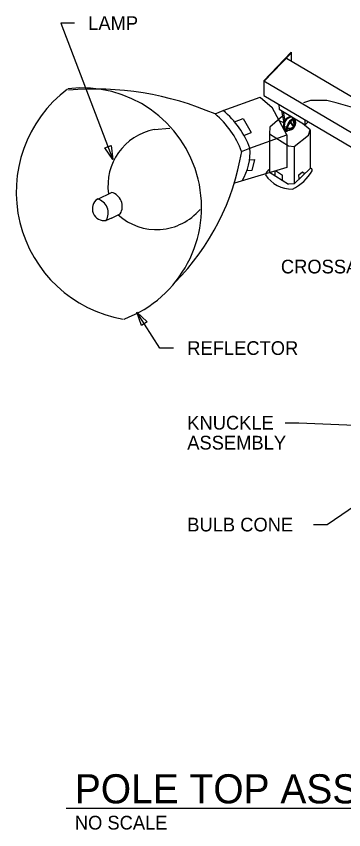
# Model space of a CAD drawing. Extents: x 10378 to 10425.2, y 10088.7 to 10132.4.
# Drawn here: x 10378.04 to 10393.97, y 10089.98 to 10129.52 of the extents above; entities that cross this region are included whole.
import ezdxf

# ---------------------------------------------------------------- set-up
doc = ezdxf.new("R2010")
doc.units = 0
for name, color, linetype in [('G-ANNO-TEXT', 7, 'Continuous'), ('G-DETL-LINE', 7, 'Continuous'), ('G-DETL-OTLN', 7, 'Continuous'), ('G-DETL-PATT', 7, 'Continuous')]:
    doc.layers.add(name, color=color, linetype=linetype)

msp = doc.modelspace()

# ---------------------------------------------------------------- linework, layer by layer
at = {"layer": 'G-ANNO-TEXT'}
for p, q in [((10380.873, 10129.184), (10380.207, 10129.184)), ((10380.207, 10129.184), (10382.744, 10122.561)), ((10385.026, 10113.39), (10383.913, 10115.142)), ((10385.693, 10113.39), (10385.026, 10113.39)), ((10391.126, 10109.759), (10391.793, 10109.759)), ((10391.793, 10109.759), (10398.213, 10109.494)), ((10393.168, 10104.808), (10398.04, 10108.165)), ((10392.501, 10104.808), (10393.168, 10104.808)), ((10380.467, 10091.02), (10423.113, 10091.02))]:
    msp.add_line(p, q, dxfattribs=at)
for points in [[(10382.662, 10123.243), (10382.744, 10122.561), (10382.35, 10123.123)], [(10384.13, 10114.49), (10383.913, 10115.142), (10384.411, 10114.668)]]:
    msp.add_lwpolyline(points, close=True, dxfattribs=at)
at = {"layer": 'G-DETL-LINE'}
for p, q in [((10390.82, 10125.223), (10390.825, 10124.995)), ((10390.997, 10124.669), (10390.382, 10124.131)), ((10390.825, 10124.995), (10392.095, 10124.233)), ((10390.945, 10124.923), (10391.062, 10124.348)), ((10391.028, 10124.873), (10391.113, 10124.457)), ((10390.847, 10124.436), (10391.065, 10124.348)), ((10392.334, 10123.998), (10391.973, 10124.305)), ((10392.095, 10124.233), (10392.095, 10124.471)), ((10392.095, 10124.233), (10392.249, 10124.38)), ((10390.382, 10124.131), (10390.356, 10123.81)), ((10390.971, 10124.177), (10391.217, 10124.136)), ((10391.125, 10123.966), (10391.161, 10123.978)), ((10391.125, 10123.893), (10391.125, 10123.966)), ((10391.161, 10123.893), (10391.161, 10123.978)), ((10391.179, 10123.893), (10391.179, 10124.038)), ((10391.215, 10123.893), (10391.215, 10124.049)), ((10392.253, 10123.73), (10392.334, 10123.998)), ((10392.334, 10123.998), (10392.334, 10122.125)), ((10390.356, 10123.81), (10390.356, 10121.938)), ((10390.356, 10123.81), (10391.291, 10123.222)), ((10391.558, 10123.195), (10392.253, 10123.73)), ((10391.291, 10123.222), (10391.558, 10123.195)), ((10391.558, 10123.195), (10391.558, 10121.376)), ((10390.356, 10121.938), (10391.291, 10121.349)), ((10390.63, 10121.766), (10390.63, 10121.998)), ((10390.651, 10122.022), (10391.001, 10121.786)), ((10392.334, 10122.125), (10391.558, 10121.376)), ((10391.78, 10121.811), (10391.959, 10121.96)), ((10391.959, 10121.96), (10392.067, 10121.868)), ((10391.001, 10121.534), (10391.001, 10121.786)), ((10391.798, 10121.617), (10391.78, 10121.811)), ((10391.558, 10121.376), (10391.291, 10121.349))]:
    msp.add_line(p, q, dxfattribs=at)
for centre, radius, start, end in [((10391.479, 10124.221), 0.436, 100.2717, 215.8313), ((10391.479, 10124.221), 0.4, 94.0056, 217.4608), ((10391.864, 10123.968), 0.688, 118.8543, 174.2368), ((10391.922, 10123.904), 0.722, 118.1089, 168.3754), ((10391.263, 10124.345), 0.375, 265.3953, 31.5556), ((10391.245, 10124.063), 0.289, 20.663, 69.297), ((10391.249, 10124.117), 0.281, 12.7976, 63.9539), ((10391.16, 10124.277), 0.395, 347.8326, 31.9067), ((10391.201, 10124.288), 0.395, 349.7008, 34.0489), ((10391.319, 10124.432), 0.356, 253.9647, 301.1435), ((10391.293, 10124.425), 0.382, 259.327, 302.5745), ((10391.632, 10124.093), 0.133, 95.1644, 192.366), ((10390.49, 10121.756), 0.328, 134.8398, 171.2692), ((10390.43, 10121.874), 0.207, 111.139, 146.0525), ((10390.434, 10123.197), 2.331, 296.6306, 329.3358), ((10392.358, 10122.042), 0.087, 337.3261, 106.4069), ((10391.467, 10122.683), 1.57, 213.9622, 270.399)]:
    msp.add_arc(centre, radius, start, end, dxfattribs=at)
at = {"layer": 'G-DETL-OTLN'}
for p, q in [((10390.083, 10126.387), (10391.421, 10127.779)), ((10390.109, 10126.363), (10391.421, 10127.728)), ((10391.182, 10127.479), (10424.91, 10107.581)), ((10391.421, 10127.779), (10391.421, 10127.339)), ((10390.083, 10126.387), (10390.083, 10125.666)), ((10390.083, 10126.387), (10423.843, 10106.471)), ((10388.113, 10124.931), (10389.912, 10125.589)), ((10389.912, 10125.589), (10390.49, 10125.085)), ((10390.083, 10125.666), (10423.843, 10105.749)), ((10391.208, 10123.759), (10390.49, 10125.085)), ((10387.711, 10124.77), (10388.113, 10124.931)), ((10388.656, 10124.391), (10389.076, 10124.556)), ((10389.076, 10124.556), (10389.468, 10123.862)), ((10384.753, 10124.009), (10385.506, 10124.071)), ((10389.119, 10123.725), (10389.468, 10123.862)), ((10389.408, 10123.1), (10391.208, 10123.759)), ((10391.208, 10123.759), (10391.212, 10122.17)), ((10389.006, 10122.939), (10389.408, 10123.1)), ((10389.388, 10122.537), (10389.628, 10122.562)), ((10389.628, 10122.562), (10389.503, 10122.028)), ((10391.212, 10122.17), (10388.651, 10121.409)), ((10389.503, 10122.028), (10389.256, 10121.998)), ((10382.009, 10120.63), (10382.672, 10120.956)), ((10382.682, 10119.709), (10382.418, 10119.594)), ((10382.682, 10119.709), (10383.099, 10119.908))]:
    msp.add_line(p, q, dxfattribs=at)
for centre, radius, start, end in [((10384.31, 10120.974), 6.27, 127.0508, 260.2516), ((10381.252, 10120.232), 5.802, 290.5252, 96.7772), ((10381.856, 10111.177), 14.8, 66.6981, 94.9636), ((10384.936, 10121.432), 4.34, 20.324, 50.2663), ((10385.338, 10121.593), 4.34, 20.324, 50.2663), ((10385.282, 10121.279), 2.781, 100.978, 188.121), ((10386.69, 10122.915), 2.725, 329.2732, 3.9034), ((10377.506, 10124.804), 11.651, 315.1694, 350.7902), ((10382.494, 10120.274), 0.705, 329.3691, 75.3618), ((10382.317, 10120.161), 0.576, 124.6885, 280.0424), ((10381.811, 10119.953), 0.705, 329.3691, 75.3618), ((10384.863, 10121.931), 2.781, 228.0701, 319.6224)]:
    msp.add_arc(centre, radius, start, end, dxfattribs=at)
at = {"layer": 'G-DETL-PATT'}
msp.add_lwpolyline([(10405.342, 10118.577), (10401.582, 10120.857), (10399.759, 10121.655), (10398.278, 10122.453), (10396.911, 10123.479), (10395.43, 10124.505), (10394.404, 10125.075), (10393.607, 10125.303), (10393.151, 10125.417), (10392.354, 10125.417), (10392.012, 10125.303)], dxfattribs=at)

# ---------------------------------------------------------------- texts
at = {"layer": 'G-ANNO-TEXT'}
for s, height, p in [('LAMP', 0.6667, (10381.54, 10128.851)), ('CROSSARM', 0.6667, (10390.915, 10117.017)), ('REFLECTOR', 0.6667, (10386.36, 10113.056)), ('KNUCKLE', 0.6667, (10386.36, 10109.426)), ('ASSEMBLY', 0.6667, (10386.36, 10108.457)), ('BULB CONE', 0.6667, (10386.36, 10104.475)), ('POLE TOP ASSEMBLY ELECTRICAL DETAIL', 1.41667, (10380.89, 10091.256)), ('NO SCALE', 0.6667, (10380.89, 10089.985))]:
    msp.add_text(s, height=height, dxfattribs=at).set_placement(p)

doc.saveas('drawing.dxf')
